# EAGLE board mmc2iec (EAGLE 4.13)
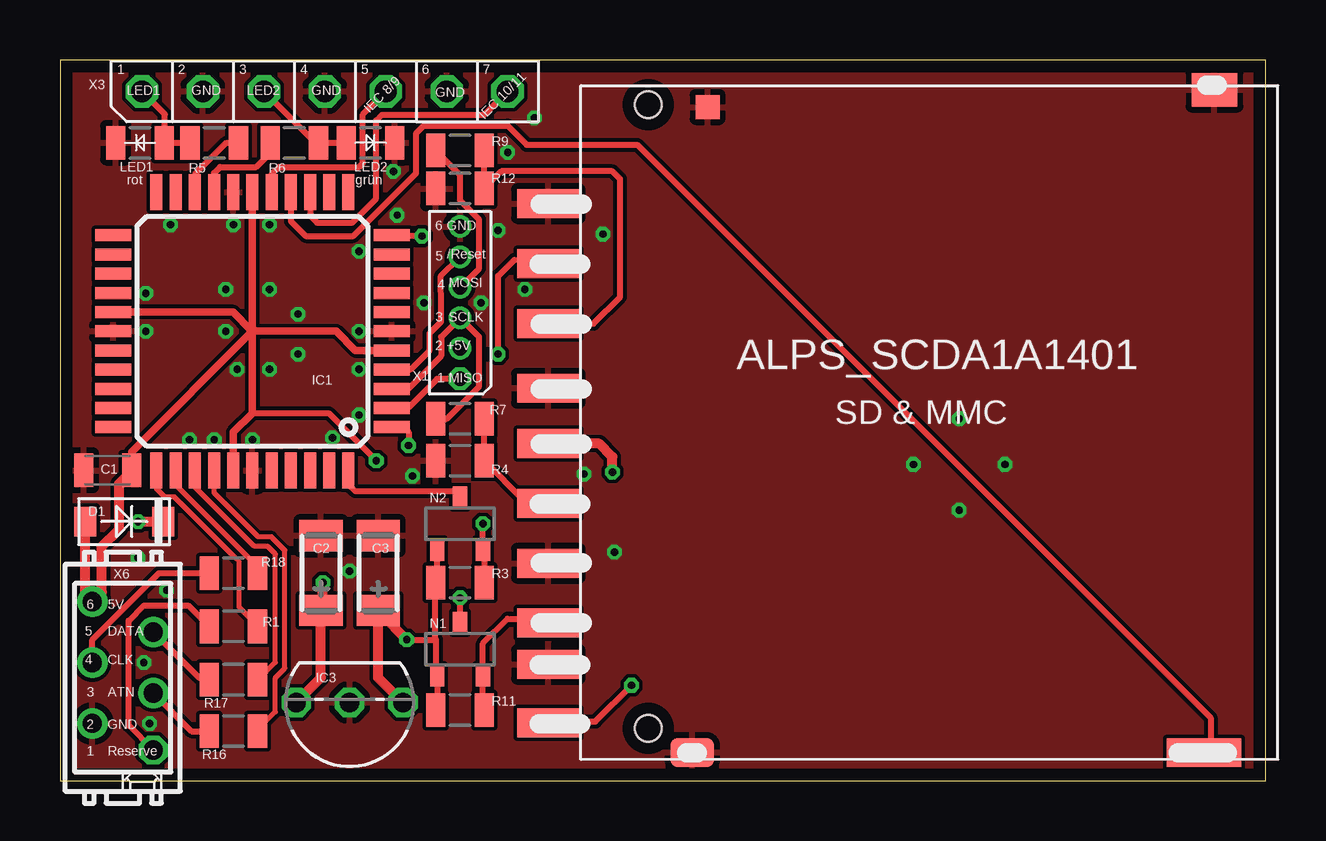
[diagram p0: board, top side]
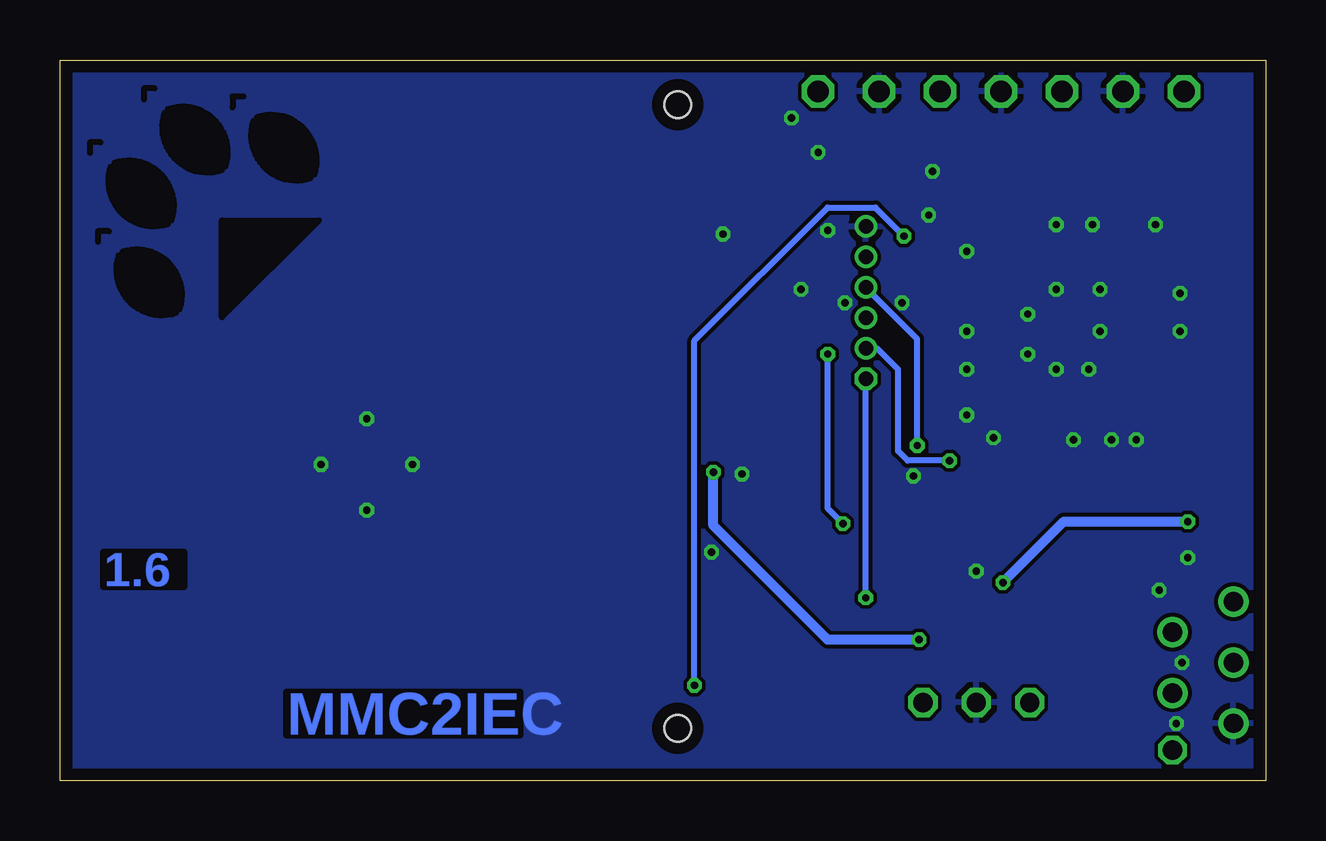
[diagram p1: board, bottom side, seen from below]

Size 50.24 x 30.04 mm. Coordinates in mm from the lower left corner, seen from the top.
Outline: 0,0 50.24,0 50.24,30.04 0,30.04 0,0
Copper layers (1*16): Top 0.035mm / dielectric 1.5mm / Bottom 0.035mm
Design rules "default": minimum track width 8mil, minimum drill 12mil, track to track 0.16mm, track to pad 0.16mm, pad to pad 0.16mm, via to via 0.16mm, smd to smd 0.16mm, copper to edge 20mil, drill to drill 8mil, minimum pad ring 6mil, minimum via ring 6mil, stop-mask expansion 4mil, vias tented up to drill 12mil, thermal gap 10mil

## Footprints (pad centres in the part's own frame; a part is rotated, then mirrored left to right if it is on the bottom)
C0805 = smd 0.8 x 1.4: 1 -1,0; 2 1,0
C_TANTAL_A = smd 1.3 x 1.8: 1 1.559,0; 2 -1.559,0
SOD-123 = smd 0.91 x 1.22: 1 -1.63,0; 2 1.63,0
TQFP44 = smd 1.5 x 0.5: 1 -5.8,4; 2 -5.8,3.2; 3 -5.8,2.4; 4 -5.8,1.6; 5 -5.8,0.8; 6 -5.8,0; 7 -5.8,-0.8; 8 -5.8,-1.6; 9 -5.8,-2.4; 10 -5.8,-3.2; 11 -5.8,-4; 23 5.8,-4; 24 5.8,-3.2; 25 5.8,-2.4; 26 5.8,-1.6; 27 5.8,-0.8; 28 5.8,0; 29 5.8,0.8; 30 5.8,1.6; 31 5.8,2.4; 32 5.8,3.2; 33 5.8,4 | smd 0.5 x 1.5: 12 -4,-5.8; 13 -3.2,-5.8; 14 -2.4,-5.8; 15 -1.6,-5.8; 16 -0.8,-5.8; 17 0,-5.8; 18 0.8,-5.8; 19 1.6,-5.8; 20 2.4,-5.8; 21 3.2,-5.8; 22 4,-5.8; 34 4,5.8; 35 3.2,5.8; 36 2.4,5.8; 37 1.6,5.8; 38 0.8,5.8; 39 0,5.8; 40 -0.8,5.8; 41 -1.6,5.8; 42 -2.4,5.8; 43 -3.2,5.8; 44 -4,5.8
TO92 = drill 0.8 pad 1.219 octagon: 1 2.223,0; 2 0,0; 3 -2.223,0
LED0805 = smd 0.8 x 1.4: 1 -1.009,0; 2 1.009,0
SOT23 = smd 0.6 x 0.9: 1 -0.95,-1.1; 2 0.95,-1.1; 3 0,1.1
R0805 = smd 0.8 x 1.4: 1 -1.009,0; 2 1.009,0
1X6_ISP = drill 0.6 pad 0.94 octagon: 1 0,0 | drill 0.6 pad 0.94 round: 2 1.27,0; 3 2.54,0; 4 3.81,0; 5 5.08,0; 6 6.35,0
ALPS_SCDA1A1401 = smd 2.6 x 1.2: 1 -4.176,6.875; 2 -4.176,4.375; 3 -4.176,1.675; 4 -4.176,-0.625; 5 -4.176,-3.125; 6 -4.176,-5.625; 7 -4.176,-8.109; 8 -4.176,-9.841; 9 -4.176,9.37; 10 -4.176,-12.275 | smd 1.8 x 1.2: 11 1.814,-13.516 | smd 3.1 x 1.2: 12 23.137,-13.517 | smd 1.9 x 1.4: 13 23.576,14.113 | smd 1 x 1: 14 2.463,13.399 | hole 1.1: -0.02,13.495; -0.019,-12.505
1X7 = drill 0.9 octagon: 1 -7.62,0; 2 -5.08,0; 3 -2.54,0; 4 0,0; 5 2.54,0; 6 5.08,0; 7 7.62,0
MICROMATCH-6 = drill 0.8 pad 1.118 octagon: 1 3.016,1.27 | drill 0.8 pad 1.27 round: 2 1.905,-1.27; 3 0.635,1.27; 4 -0.635,-1.27; 5 -1.905,1.27; 6 -3.175,-1.27

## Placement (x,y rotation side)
C1  100n  [C0805]  1.98,12.94 0 top
C2  4µ7  [C_TANTAL_A]  10.87,8.65 270 top
C3  4µ7  [C_TANTAL_A]  13.26,8.65 270 top
D1  4148  [SOD-123]  2.68,10.79 180 top
IC1  MEGA32  [TQFP44]  8.02,18.73 180 top
IC3  [TO92]  12.06,3.25 180 top
LED1  [LED0805]  3.33,26.59 0 top
LED2  [LED0805]  12.94,26.59 180 top
N1  BSN20  [SOT23]  16.67,5.48 0 top
N2  BSN20  [SOT23]  16.67,10.72 0 top
R1  nB  [R0805]  7.22,6.43 0 top
R3  4k7  [R0805]  16.67,8.25 180 top
R4  6k8  [R0805]  16.67,13.34 180 top
R5  560  [R0805]  6.43,26.59 180 top
R6  560  [R0805]  9.76,26.59 0 top
R7  4k7  [R0805]  16.67,15.08 180 top
R9  4k7  [R0805]  16.67,26.27 180 top
R11  4k7  [R0805]  16.67,2.94 0 top
R12  6k8  [R0805]  16.67,24.69 180 top
R16  100  [R0805]  7.22,2.06 0 top
R17  100  [R0805]  7.22,4.21 0 top
R18  100  [R0805]  7.22,8.65 0 top
U$1  [LOGO]  43.5,23.36 315 top
X1  [1X6_ISP]  16.67,16.75 90 top
X2  [ALPS_SCDA1A1401]  24.53,14.68 0 top
X3  [1X7]  11.03,28.73 0 top
X6  [MICROMATCH-6]  2.62,4.29 270 top

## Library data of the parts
C1-C3 D1 IC1 IC3 LED1 LED2 N1 N2 R1 R3-R7 R9 R11 R12 R16-R18 U$1 X1-X3 X6 = 0_rr

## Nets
3V0: C3.1 IC3.3 N1.1 N2.1 R3.2 R11.1 X2.4
+5V: C1.2 D1.2 IC1.5 IC1.17 IC1.27 IC1.38 X1.2 X6.6
/RESET: IC1.4 X1.5
ATN: IC1.37 R16.2
CD: IC1.11 X2.10
CLK: IC1.35 R18.2
CS: IC1.44 N2.3
CSX: N2.2 R3.1 X2.1
DATA: IC1.36 R17.2
GND: C1.1 C2.2 C3.2 IC1.6 IC1.18 IC1.28 IC1.39 IC3.2 LED1.1 LED2.1 R4.2 R12.2 X1.6 X2.3 X2.6 X2.8 X2.9 X2.11 X2.13 X2.14 X3.2 X3.4 X3.6 X6.2
MISO: IC1.2 N1.3 X1.1
MISOX: N1.2 R11.2 X2.7
MOSI: IC1.1 R9.2 X1.4
N$1: IC1.14 X3.7
N$2: C2.1 D1.1 IC3.1
N$3: R4.1 R7.1 X2.5
N$5: R9.1 R12.1 X2.2
N$7: R18.1 X6.4
N$8: LED1.2 R5.2 X3.1
N$9: LED2.2 R6.2 X3.3
N$10: IC1.16 X3.5
N$11: R17.1 X6.5
N$12: R16.1 X6.3
N$13: R1.1 X6.1
N$14: IC1.34 R1.2
PC0: IC1.19 R6.1
PC1: IC1.20 R5.1
SCK: IC1.3 R7.2 X1.3
WP: IC1.15 X2.12

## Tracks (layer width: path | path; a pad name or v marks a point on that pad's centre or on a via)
3V0  (via drill 0.3)
  Top 0.254: 15.72,8.18 15.66,8.23 R3.2 | N2.1 15.72,8.18 | 15.65,4.38 15.64,4.37 | 15.65,4.38 N1.1 15.72,3.02 15.64,2.94 | 15.65,4.38 15.66,4.39 15.66,5.87 15.64,5.87 | 15.64,2.94 | 15.64,2.94 R11.1 | v14.45,5.87 15.64,5.87 | 15.72,8.18 15.64,8.18 15.64,5.87
  Top 0.406: v23.02,12.86 23.02,13.49 22.46,14.05 20.8,14.05 20.81,14.06 X2.4 | IC3.3 | IC3.3 13.26,4.29 C3.1 13.18,7.01 13.18,6.99 13.34,6.99 v14.45,5.87
  Bottom 0.406: v23.02,12.86 23.02,10.64 18.26,5.87 v14.45,5.87
+5V  (via drill 0.3)
  Top 0.254: 8.1,18.73 8.1,18.81 | 8.01,15.31 8.02,15.32 11.19,15.32 v13.18,13.34
  Top 0.305: IC1.38 7.22,14.53 8.01,15.31 8.02,18.73 | IC1.5 12.31,17.93 11.51,18.73 8.1,18.73 8.02,18.73 | IC1.27 7.22,19.53 7.98,18.77 | 8.02,18.73 7.98,18.77 | 7.98,18.77 8.02,18.81 IC1.17 | C1.2 2.98,13.7 8.02,18.73
  Top 0.406: X6.6 | X6.6 1.75,7.86 1.75,9.76 2.46,10.48 2.46,12.38 2.98,12.91 C1.2 | X6.6 | D1.2 1.05,7.76 X6.6
  Bottom 0.254: X1.2 16.19,18.02 15.32,17.15 15.32,13.73 14.92,13.34 v13.18,13.34
/RESET
  Top 0.254: X1.5 15.88,21.03 15.88,19.69 15.88,19.13 15.4,18.65 15.4,17.94 14.61,17.15 13.73,17.15 13.74,17.13 IC1.4
ATN
  Top 0.203: IC1.37 6.42,12 8.26,10.16 8.81,10.16 9.37,9.6 9.37,4.68 8.97,4.29 8.97,2.86 8.18,2.06 | 8.18,2.06 | R16.2 8.18,2.06
CD  (via drill 0.3)
  Top 0.254: IC1.11 13.85,22.7 v15.08,22.7 | X2.10 20.88,2.46 22.3,2.46 v23.81,3.97
  Bottom 0.254: v15.08,22.7 16.27,23.89 18.26,23.89 23.81,18.34 v23.81,3.97
CLK
  Top 0.203: 8.26,8.57 8.23,8.6 R18.2 8.23,8.79 8.26,8.89 4.82,12.33 IC1.35
CS
  Top 0.254: IC1.44 12.02,12.35 12.3,12.07 16.43,12.07 N2.3 | N2.3 | N2.3
CSX  (via drill 0.3)
  Top 0.254: R3.1 17.68,9.55 17.62,9.61 N2.2 17.62,9.53 v17.62,10.72 | X2.1 18.94,21.72 18.26,21.03 v18.26,17.78
  Bottom 0.254: v18.26,17.78 18.26,11.35 v17.62,10.72
DATA
  Top 0.203: R17.2 8.26,4.21 8.97,4.92 8.97,9.45 8.65,9.76 8.1,9.76 5.64,12.22 5.64,12.78 5.62,12.8 IC1.36
GND  (via drill 0.3)
  Top 0.254: R4.2 15.72,13.34
  other vias: 14.05,23.57 8.73,23.18 12.46,18.73 12.46,17.15 7.22,23.18 3.57,18.73 7.38,17.15 12.46,22.07 11.35,14.29 8.02,14.21 6.43,14.21 5.4,14.21 14.68,12.7 21.83,12.78 17.54,19.92 19.37,20.48 8.73,20.48 6.91,20.48 3.57,20.32 4.6,23.18 9.92,19.45 8.73,17.15 9.92,17.78 12.46,15.24 13.89,25.4 19.76,27.62 18.26,22.94 22.62,22.78 18.65,26.19 3.25,9.29 23.1,9.53 6.91,18.73 35.56,13.18 37.46,11.27 39.37,13.18 37.46,15.08 15.16,19.92 3.73,2.38 4.44,7.94 3.49,4.92 12.06,8.73
  pour Top: 0,0 0,30.08 50.24,30.08 50.24,0
  pour Bottom: 0,0 0,30.08 50.24,30.08 50.24,0
MISO  (via drill 0.3)
  Top 0.254: X1.1 15.72,16.75 14.53,15.56 13.65,15.56 13.68,15.53 IC1.2 | N1.3 v16.67,7.62 | v16.67,7.62
  Bottom 0.254: X1.1 | X1.1 | v16.67,7.62 X1.1
MISOX
  Top 0.254: R11.2 17.62,2.99 N1.2 17.62,5.71 18.65,6.75 20.8,6.75 20.81,6.73 X2.7
MOSI  (via drill 0.3)
  Top 0.254: IC1.1 14.32,14.73 14.53,14.53 v14.53,13.97 | X1.4 17.46,21.35 17.46,23.39 16.67,24.18 16.67,25.24 15.88,26.03 R9.2
  Bottom 0.254: X1.4 | X1.4 | v14.53,13.97 14.53,18.42 X1.4
N$1
  Top 0.254: IC1.14 10.42,23.56 10.72,23.26 12.17,23.26 13.18,24.26 13.18,27.52 13.41,27.75 17.67,27.75 X3.7 | X3.7
N$2  (via drill 0.3)
  Top 0.406: D1.1 4.37,10.8 v3.25,10.8 | v10.95,8.26 10.95,7.06 10.93,7.09 C2.1 10.87,4.29 IC3.1 | IC3.1
  Bottom 0.406: v3.25,10.8 8.41,10.8 v10.95,8.26
N$3
  Top 0.254: 17.68,13.28 | 17.68,13.28 R4.1 19.34,11.67 20.8,11.67 20.8,11.59 X2.5 | 17.68,13.28 R7.1 | 17.68,13.28 17.7,13.26
N$5
  Top 0.254: X2.2 20.87,19.06 20.88,19.05 22.23,19.05 23.34,20.16 23.34,25.08 23.02,25.4 18.39,25.4 R12.1 17.68,24.63 | 17.68,24.63 R9.1 | 17.68,24.63 17.7,24.61
N$7
  Top 0.254: R18.1 4.13,8.65 1.35,5.87 X6.4 | X6.4 | X6.4
N$8
  Top 0.254: 4.37,26.59 R5.2 | 4.37,26.59 LED1.2 4.37,26.59 | 4.37,26.59 | X3.1 4.37,27.78 4.37,26.59
N$9
  Top 0.254: LED2.2 R6.2 10.72,26.53 10.72,26.51 | X3.3 10.72,26.51 | 10.72,26.51
N$10
  Top 0.254: IC1.16 8.82,25.27 9.13,25.58 12.46,25.58 12.62,25.74 12.62,27.78 X3.5 | X3.5
N$11
  Top 0.254: R17.1 6.27,4.26 6.27,4.29 5.79,4.29 X6.5
N$12
  Top 0.254: R16.1 | X6.3 5.48,2.06 R16.1
N$13
  Top 0.254: R1.1 5.34,7.3 3.49,7.3 2.86,6.67 2.86,2.3 X6.1 | X6.1 | X6.1
N$14
  Top 0.203: IC1.34 4.02,12.18 4.37,11.83 4.76,11.83 | R1.2 8.26,6.43 7.46,7.22 7.46,9.13 7.3,9.29 4.76,11.83 | 4.76,11.83
PC0
  Top 0.254: IC1.19 6.42,25.33 6.67,25.58 8.18,25.58 8.75,26.16 R6.1
PC1
  Top 0.254: IC1.20 5.62,25.28 6.93,26.59 7.38,26.59 | 7.38,26.59 | 7.38,26.59 R5.1
SCK
  Top 0.254: IC1.3 14.51,16.33 15.88,17.7 15.88,18.49 X1.3 | R7.2 16.11,15.08 17.46,16.43 17.46,18.49 X1.3 | X1.3 | X1.3
WP
  Top 0.254: IC1.15 9.62,23.32 10.24,22.7 12.22,22.7 14.84,25.32 14.84,26.99 15.16,27.31 18.65,27.31 19.45,26.51 24.05,26.51 47.94,2.62 47.94,1.03 47.96,1.03 X2.12

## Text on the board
Bottom: 1.6 | MMC2IEC
tPlace: 1 | LED1 | 2 | GND | 3 | LED2 | 4 | GND | 5 | 6 | 7 | IEC 8/9 | GND | IEC 10/11 | rot | grün | 6 | GND | 5 | /Reset | MOSI | 4 | 3 | SCLK | 2 | +5V | 1 | MISO | 6 | 5V | 5 | DATA | 4 | CLK | 3 | ATN | 2 | GND | 1 | Reserve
